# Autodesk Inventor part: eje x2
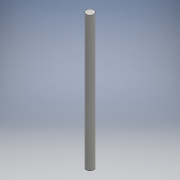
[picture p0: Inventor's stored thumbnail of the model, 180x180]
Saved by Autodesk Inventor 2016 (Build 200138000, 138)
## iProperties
Created: 2016-06
Part Number: eje x2
Material: Genérico
Document SubType Name: Modeling
Designer: adm
Density: 1 g/cm^3
Appearance: Valor por defecto
Author: adm
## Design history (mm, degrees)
sketch "Boceto1"
  geometry: C1 r 5 at (0, 0); 1 further point
  constraints: 1 centre point, 1 coincident
  dimensions: "d0" = 10 diameter of C1
extrude "Extrusión1" new body sketch "Boceto1" distance "d1" = 180; taper "d2" = 0 deg
node "Sólido1"
